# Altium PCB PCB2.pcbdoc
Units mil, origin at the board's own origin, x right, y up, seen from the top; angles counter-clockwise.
Board outline 6605 x 4585 mil, 2 copper layers (Top Layer, Bottom Layer); 123 components, 92 nets, 392 pads, 89 vias.
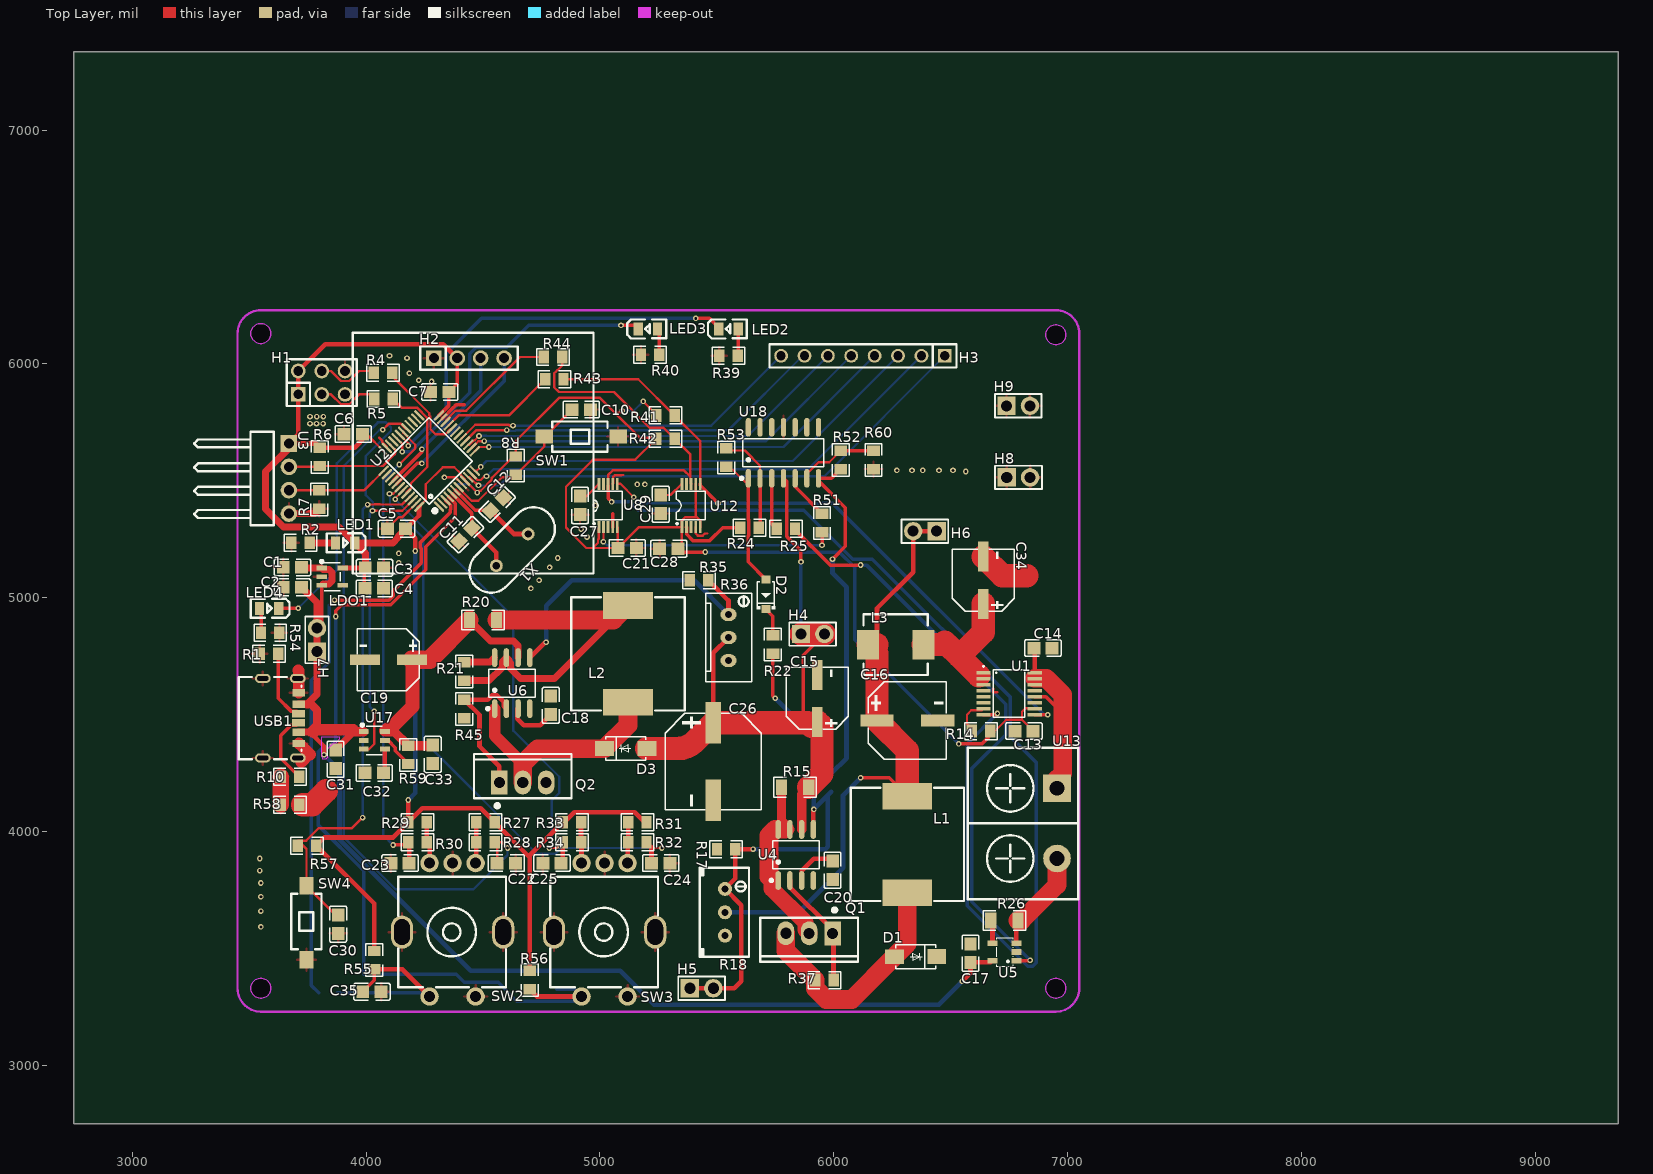
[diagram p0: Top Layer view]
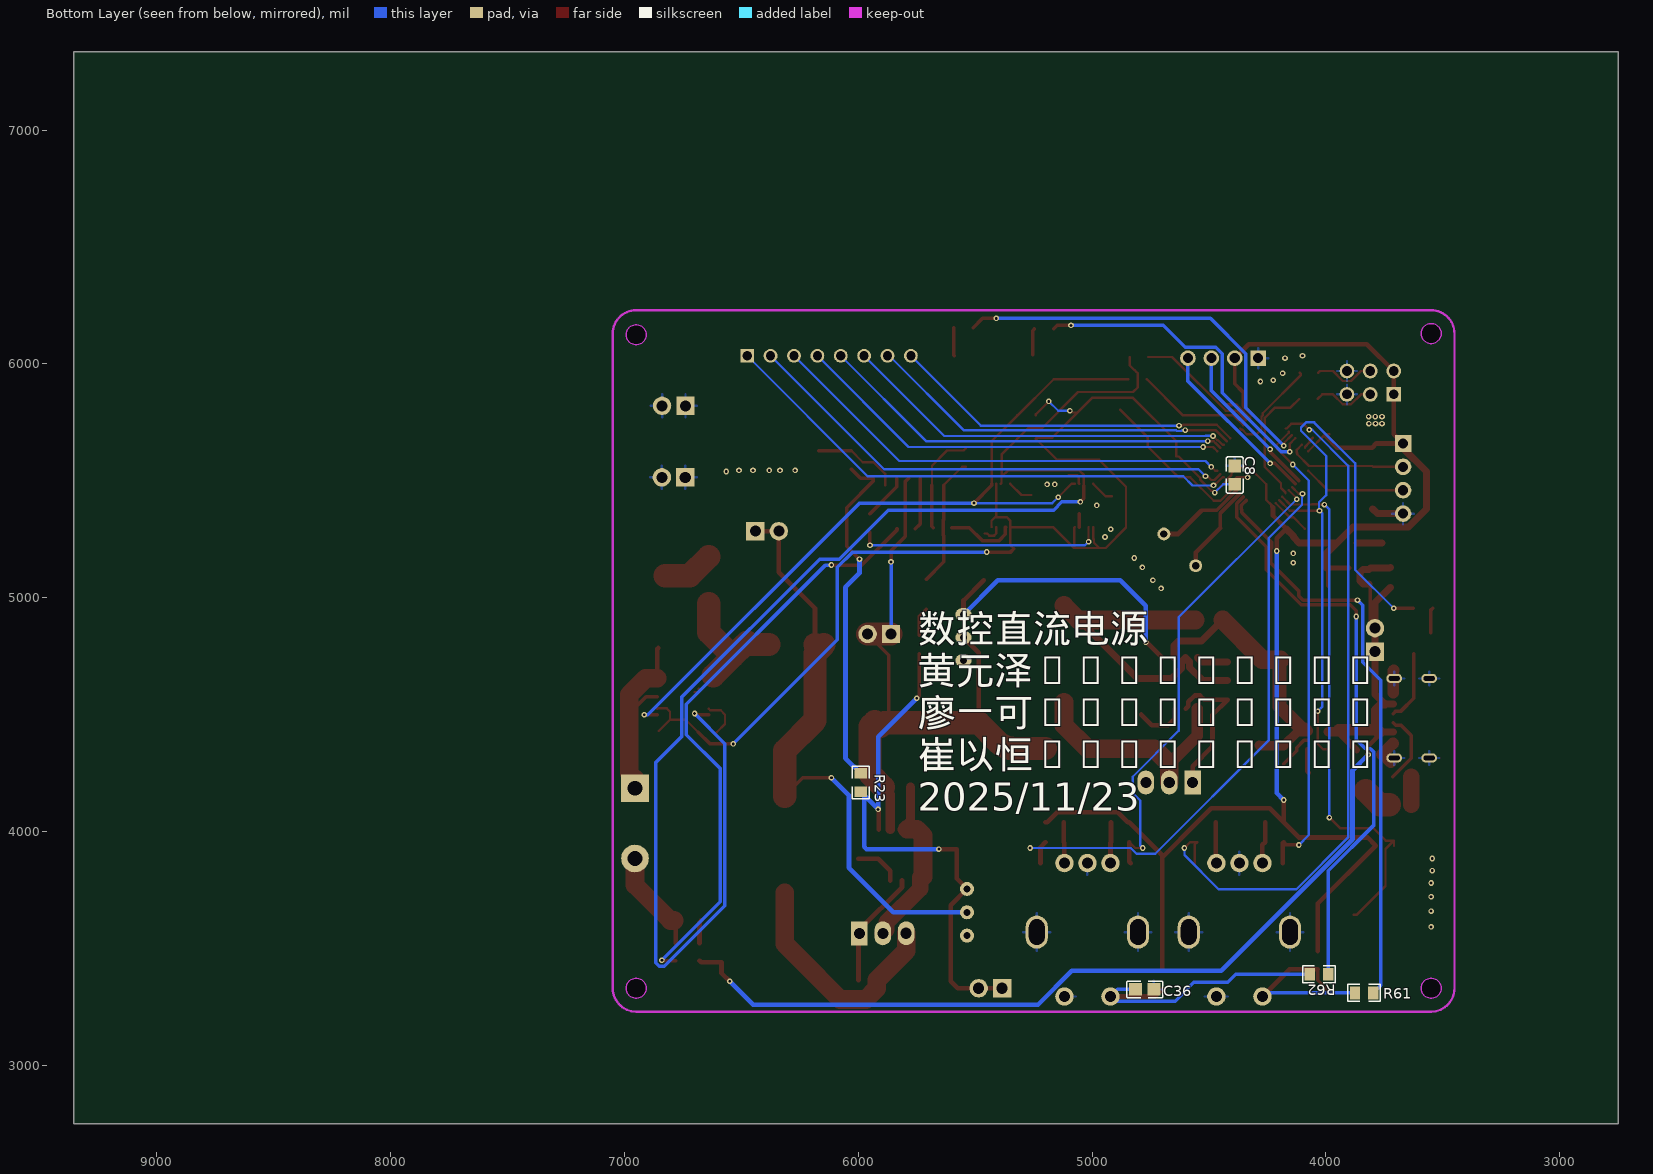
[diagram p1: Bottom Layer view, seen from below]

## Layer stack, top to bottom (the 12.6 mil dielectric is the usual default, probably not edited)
Top Layer: signal copper (thickness not stored)
Dielectric: dielectric 12.6, FR-4, Dk 4.8
Bottom Layer: signal copper (thickness not stored)

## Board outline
9355,2750 2750,2750 2750,7335 9355,7335
cut-out: 3593,6130 cw(c3550,6130) 3507,6130 cw(c3550,6130)
cut-out: 6993,6125 cw(c6950,6125) 6907,6125 cw(c6950,6125)
cut-out: 6993,3330 cw(c6950,3330) 6907,3330 cw(c6950,3330)
cut-out: 3593,3330 cw(c3550,3330) 3507,3330 cw(c3550,3330)

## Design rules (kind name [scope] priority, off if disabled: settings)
BoardOutlineClearance copperThickness1oz [All] p0: genericclearance=10 ignorepadtopadclearanceinfootprint=FALSE except(0: Arc-SplitContinuation Track-SplitContinuation SMDPad-SplitContinuation THPad-SplitContinuation Via-SplitContinuation Fill-SplitContinuation Poly-SplitContinuation Region-SplitContinuation Text-SplitContinuation; 6: Track-CutoutEdge SMDPad-CutoutEdge THPad-CutoutEdge Via-CutoutEdge Region-CutoutEdge; 11.8: Track-OutlineEdge SMDPad-OutlineEdge THPad-OutlineEdge Via-OutlineEdge Fill-OutlineEdge Region-OutlineEdge Poly-OutlineEdge Text-OutlineEdge Fill-CutoutEdge)
BoardOutlineClearance copperThickness2oz [All] p0: genericclearance=10 ignorepadtopadclearanceinfootprint=FALSE except(0: Arc-SplitContinuation Track-SplitContinuation SMDPad-SplitContinuation THPad-SplitContinuation Via-SplitContinuation Fill-SplitContinuation Poly-SplitContinuation Region-SplitContinuation Text-SplitContinuation; 6: Track-CutoutEdge SMDPad-CutoutEdge THPad-CutoutEdge Via-CutoutEdge Region-CutoutEdge; 11.8: Track-OutlineEdge SMDPad-OutlineEdge THPad-OutlineEdge Via-OutlineEdge Fill-OutlineEdge Region-OutlineEdge Poly-OutlineEdge Text-OutlineEdge Fill-CutoutEdge)
Clearance copperThickness1oz [(InNet('+5V') OR InNet('GND') OR InNet('VCC') OR InNet('RESET') OR InNet('OSCIN') OR InNet('OSCOUT') OR InNet('IN-') OR InNet('VOUT') OR InNet('$1N15305') OR InNet('$1N14143') OR InNet('PA8') OR InNet('PA9') OR InNet('PB6') OR InNet('PB7') OR InNet('$1N21810') OR InNet('$1N23905') OR InNet('$1N5169') OR InNet('$1N14411') OR InNet('$1N14439') OR InNet('$1N3483') OR InNet('$1N3468') OR InNet('PB4') OR InNet('PB5') OR InNet('PA0') OR InNet('PA1') OR InNet('PA2') OR InNet('PA3') OR InNet('PA4') OR InNet('PA5') OR InNet('PA6') OR InNet('PA7') OR InNet('I-FB') OR InNet('$1N21463') OR InNet('$1N3407') OR InNet('PB0') OR InNet('$1N36216') OR InNet('PB1') OR InNet('$1N36298') OR InNet('STEP-DOWN1') OR InNet('$1N26107') OR InNet('$1N15295') OR InNet('$1N3381') OR InNet('BOOT1') OR InNet('BOOT0') OR InNet('SWDIO') OR InNet('SWCLK') OR InNet('$1N3384') OR InNet('$1N3763') OR InNet('$1N12640') OR InNet('DAC-VOUT1') OR InNet('$1N14642') OR InNet('DAC-IOUT') OR InNet('$1N14584') OR InNet('I-VOUT') OR InNet('$1N19210') OR InNet('$1N19205') OR InNet('$1N19652') OR InNet('$1N19642') OR InNet('$1N21716') OR InNet('$1N26297') OR InNet('SCL2') OR InNet('SDA2') OR InNet('PB10') OR InNet('PB11') OR InNet('$1N65373') OR InNet('DAC-VOUT') OR InNet('$1N65377') OR InNet('VBAT') OR InNet('PC13') OR InNet('PC14') OR InNet('PC15') OR InNet('PB12') OR InNet('PB13') OR InNet('PB14') OR InNet('PB15') OR InNet('PA10') OR InNet('PA11') OR InNet('PA12') OR InNet('PA15') OR InNet('PB3') OR InNet('PB8') OR InNet('PB9') OR InNet('V-UP') OR InNet('$1N72576') OR InNet('$1N76167') OR InNet('$1N76238') OR InNet('PGND') OR InNet('+5V-SWITCH') OR InNet('RS+') OR InNet('$1N76827') OR InNet('QOD') OR InNet('VOUT-FILTER'))] p1: gap=7 ignorepadtopadclearanceinfootprint=FALSE except(4: Track-Track; 6: Track-SMDPad SMDPad-SMDPad Track-THPad SMDPad-THPad THPad-THPad Track-Via SMDPad-Via THPad-Via Via-Via SMDPad-Fill THPad-Fill Via-Fill Fill-Fill Track-Region SMDPad-Region THPad-Region Via-Region Region-Region Track-Poly SMDPad-Poly THPad-Poly Via-Poly Fill-Poly Region-Poly Poly-Poly Track-Text SMDPad-Text THPad-Text Via-Text Fill-Text Region-Text Poly-Text Text-Text; 6.9: Track-Hole SMDPad-Hole THPad-Hole Via-Hole Fill-Hole Region-Hole Poly-Hole Text-Hole Sheet-Hole; 11.8: Track-Fill Fill-Region Track-Sheet SMDPad-Sheet THPad-Sheet Via-Sheet Fill-Sheet Region-Sheet Poly-Sheet Text-Sheet)
Clearance copperThickness2oz [All] p1: gap=7 ignorepadtopadclearanceinfootprint=FALSE except(6: Track-SMDPad SMDPad-SMDPad Track-THPad SMDPad-THPad THPad-THPad Track-Via SMDPad-Via THPad-Via Via-Via SMDPad-Fill THPad-Fill Via-Fill Fill-Fill Track-Region SMDPad-Region THPad-Region Via-Region Region-Region Track-Poly SMDPad-Poly THPad-Poly Via-Poly Fill-Poly Region-Poly Poly-Poly Track-Text SMDPad-Text THPad-Text Via-Text Fill-Text Region-Text Poly-Text Text-Text; 6.9: Track-Hole SMDPad-Hole THPad-Hole Via-Hole Fill-Hole Region-Hole Poly-Hole Text-Hole Sheet-Hole; 8: Track-Track; 11.8: Track-Fill Fill-Region Track-Sheet SMDPad-Sheet THPad-Sheet Via-Sheet Fill-Sheet Region-Sheet Poly-Sheet Text-Sheet)
DiffPairsRouting differentialPair [All] p1: maxuncoupledlength=10 minlimit=6 maxlimit=6 mostfreqgap=6 toplayer_minwidth=5 toplayer_prefwidth=10 toplayer_maxwidth=100 bottomlayer_minwidth=5 bottomlayer_prefwidth=10 bottomlayer_maxwidth=100
PasteMaskExpansion pasteMaskExpansion [All] p1: expansion=0
PlaneConnect innerPlane [All] p1: planeconnectstyle=Relief reliefexpansion=20 reliefentries=4 reliefconductorwidth=10 reliefairgap=10
PolygonConnect PGND [All] p1: connectstyle=Direct reliefentries=4 reliefconductorwidth=10 polygonreliefangle="90 Angle" airgapwidth=10
PolygonConnect GND [All] p1: connectstyle=Relief reliefentries=4 reliefconductorwidth=10 polygonreliefangle="90 Angle" airgapwidth=10
RoutingVias viaSize [All] p1: viastyle="Through Hole" holewidth=12.0078 minholewidth=11.811 maxholewidth=248.0314 width=24.0158 minwidth=19.685 maxwidth=393.7008
SolderMaskExpansion solderMaskExpansion [All] p1: useseparateexpansions=TRUE expansion=2 expansionbottom=2
Width copperThickness1oz [All] p1: maxlimit=200 minlimit=5 preferedwidth=10
Width P [All] p1: maxlimit=200 minlimit=8 preferedwidth=20

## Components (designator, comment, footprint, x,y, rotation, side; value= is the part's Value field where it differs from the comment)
C1 "0805B104K500NT" C0805 3685,5130 r0 top
C2 "CL21B105KBFNNNE" C0805 3685,5045 r0 top
C3 "CL21B105KBFNNNE" C0805 4035.76,5128.37 r180 top
C4 "0805B104K500NT" C0805 4035,5040 r180 top
C5 "0805B104K500NT" C0805 4130,5295 r0 top
C6 "0805B104K500NT" C0805 3945,5700 r0 top
C7 "0805B104K500NT" C0805 4315,5880 r0 top
C8 "0805B104K500NT" C0805 4390,5525 r270 bottom
C10 "0805B104K500NT" C0805 4920,5805 r0 top
C11 "0805CG220J500NT" C0805 4425,5270 r45 top
C12 "0805CG220J500NT" C0805 4560,5400 r225 top
C13 "0805B104K500NT" C0805 6813.74,4430 r0 top
C14 "0805B474K500NT" C0805 6895,4785 r180 top
C15 "MA35V100M6X8" CAP-SMD_BD6.3-L6.6-W6.6-RD 5930,4570 r270 top
C16 "MA25V470M8x10" CAP-SMD_BD8.0-L8.3-W8.3-LS9.0-FD_H10.5 6315,4475 r0 top
C17 "0805B104K500NT" C0805 6585,3480 r90 top
C18 "0805B152K500NT" C0805 4790,4540 r270 top
C19 "MA35V100M6X8" CAP-SMD_BD6.3-L6.6-W6.6-RD 4095,4735 r0 top
C20 "0805B471K500NT" C0805 5995,3835 r90 top
C21 "0805B104K500NT" C0805 5116.32,5213.02 r180 top
C22 "0805B103K500NT_C52278" C0805 4600,3865 r0 top
C23 "0805B103K500NT_C52278" C0805 4145,3865 r0 top
C24 "0805B103K500NT_C52278" C0805 5260,3865 r0 top
C25 "0805B103K500NT_C52278" C0805 4795,3865 r0 top
C26 "MA35V330M10x10" CAP-SMD_BD10.0-L10.3-W10.3-FD-LS11.0_H12.0 5485,4300 r270 top
C27 "0805B224K500NT" C0805 4915,5395 r90 top
C28 "0805B104K500NT" C0805 5295,5210 r0 top
C29 "0805B224K500NT" C0805 5260,5400 r90 top
C30 "0805B104K500NT" C0805 3880.63,3604.37 r270 top
C31 "CL21B105KBFNNNE" C0805 3869.59,4308.81 r90 top
C32 "0805B471K500NT" C0805 4034.11,4251.28 r180 top
C33 "CL21A106KAYNNNE_C15850" C0805 4285,4330 r270 top
C34 "MA35V100M6X8" CAP-SMD_BD6.3-L6.6-W6.6-RD 6640,5075 r270 top
C35 "0805B103K500NT_C52278" C0805 4025,3315 r0 top
C36 "0805B103K500NT_C52278" C0805 4775,3325 r180 bottom
D1 "SS34_C7420365" SMA_L4.3-W2.6-LS5.0-FD 6350,3465 r0 top
D2 "1N4148W_C7420318" SOD-123_L2.7-W1.6-LS3.7-FD 5710,5015 r270 top
D3 "SS34_C7420365" SMA_L4.3-W2.6-LS5.0-FD 5110,4355 r180 top
H1 "210-72-03GB01" HDR-TH_6P-P2.54-V-R2-C3-S2.54_A2541WV-2X3P 3810,5920 r0 top
H2 "2.54-1*4P母" HDR-TH_4P-P2.54-V-F 4440,6025 r0 top
H3 "PZ254V-11-08P" HDR-TH_8P-P2.54-V-M 6125,6035 r180 top
H4 "PZ254V-11-02P" HDR-TH_2P-P2.54-V-M 5910,4845 r0 top
H5 "PZ254V-11-02P" HDR-TH_2P-P2.54-V-M 5435,3330 r0 top
H6 "PZ254V-11-02P" HDR-TH_2P-P2.54-V-M 6390,5285 r180 top
H7 "PZ254V-11-02P" HDR-TH_2P-P2.54-V-M 3790,4820 r90 top
H8 "PZ254V-11-02P" HDR-TH_2P-P2.54-V-M 6790,5515 r0 top
H9 "PZ254V-11-02P" HDR-TH_2P-P2.54-V-M 6789,5821.15 r0 top
L1 "SMDRI127-221MT" IND-SMD_L12.3-W12.3_SMDRI127 6315,3945 r270 top
L2 "SMDRI127-221MT" IND-SMD_L12.3-W12.3_SMDRI127 5120,4760 r90 top
L3 "FXL0630-1R0-M" IND-SMD_L7.0-W6.6 6265,4800 r0 top
LDO1 "ME6211C33M5G-N" SOT-23-5_L3.0-W1.7-P0.95-LS2.8-BL 3855,5090 r270 top
LED1 "NCD0805B2" LED0805-R-RD 3910,5235 r180 top
LED2 "NCD0805B2" LED0805-R-RD 5550,6150 r0 top
LED3 "NCD0805B2" LED0805-R-RD 5205,6150 r0 top
LED4 "NCD0805B2" LED0805-R-RD 3585,4955 r180 top
Q1 "TIP31C_C963401" TO-220-3_L10.0-W4.5-P2.54-L 5895,3565 r180 top
Q2 "TIP31C_C963401" TO-220-3_L10.0-W4.5-P2.54-L 4670,4210 r0 top
R1 "0805W8F5101T5E" R0805 3585,4760 r180 top
R2 "0805W8F1001T5E" R0805 3720,5235 r180 top
R4 "0805W8F1002T5E_C17414" R0805 4072.5,5962.5 r0 top
R5 "0805W8F1002T5E_C17414" R0805 4075,5850 r180 top
R6 "0805W8F1002T5E_C17414" R0805 3801.39,5603.01 r270 top
R7 "0805W8F1002T5E_C17414" R0805 3800,5420 r90 top
R8 "0805W8F1002T5E_C17414" R0805 4640,5565 r90 top
R10 "0805W8F5101T5E" R0805 3675,4235 r180 top
R14 "0805W8F4701T5E" R0805 6630,4430 r180 top
R15 "FRL1206FR220TS" R1206 5835,4190 r180 top
R17 "0805W8F1002T5E_C17414" R0805 5540,3925 r0 top
R18 "3296W-1-104LF" RES-ADJ-TH_3296W 5535,3655 r0 top
R20 "FRL1206FR220TS" R1206 4500,4905 r180 top
R21 "0805W8F1800T5E" R0805 4420,4685 r270 top
R22 "0805W8F1001T5E" R0805 5740,4800 r90 top
R23 "0805W8F1002T5E_C17414" R0805 5990,4210 r270 bottom
R24 "0805W8F1001T5E" R0805 5640,5300 r0 top
R25 "0805W8F1001T5E" R0805 5795,5295 r180 top
R26 "RE1206F1R050" R1206 6730,3620 r180 top
R27 "0805W8F1002T5E_C17414" R0805 4510,4040 r0 top
R28 "0805W8F1002T5E_C17414" R0805 4510,3955 r180 top
R29 "0805W8F1002T5E_C17414" R0805 4220,4040 r0 top
R30 "0805W8F1002T5E_C17414" R0805 4220,3955 r0 top
R31 "0805W8F1002T5E_C17414" R0805 5160,4040 r0 top
R32 "0805W8F1002T5E_C17414" R0805 5160,3955 r180 top
R33 "0805W8F1002T5E_C17414" R0805 4880,4040 r0 top
R34 "0805W8F1002T5E_C17414" R0805 4880,3955 r0 top
R35 "0805W8F1002T5E_C17414" R0805 5423.74,5075 r0 top
R36 "3296W-1-104_C48997936" RES-ADJ-TH_3296W-1-203 5550,4830 r90 top
R37 "0805W8F1000T5E" R0805 5960,3365 r0 top
R39 "0805W8F1001T5E" R0805 5550,6035 r180 top
R40 "0805W8F1001T5E" R0805 5215,6040 r180 top
R41 "0805W8F1002T5E_C17414" R0805 5280,5780 r0 top
R42 "0805W8F1002T5E_C17414" R0805 5280,5680 r0 top
R43 "0805W8F1000T5E" R0805 4805,5935 r180 top
R44 "0805W8F1000T5E" R0805 4800,6030 r180 top
R45 "0805W8F1800T5E" R0805 4420,4525 r270 top
R51 "0805W8F1001T5E" R0805 5950,5320 r90 top
R52 "0805W8F1001T5E" R0805 6030,5590 r270 top
R53 "0805W8F1001T5E" R0805 5540,5600 r270 top
R54 "0805W8F1001T5E" R0805 3590,4850 r0 top
R55 "0805W8F1002T5E_C17414" R0805 4035,3450 r90 top
R56 "0805W8F1002T5E_C17414" R0805 4700,3365 r270 top
R57 "0805W8F1002T5E_C17414" R0805 3747.89,3940.15 r0 top
R58 "Res_0805" R0805 3675,4115 r0 top
R59 "0805W8F1800T5E" R0805 4179.89,4328.35 r270 top
R60 "0805W8F1001T5E" R0805 6170,5590 r90 top
R61 "0805W8F1002T5E_C17414" R0805 3836.26,3310 r0 bottom
R62 "0805W8F1002T5E_C17414" R0805 4030,3390 r0 bottom
SW1 "TS-1101-C-W" SW-SMD_L6.0-W3.3-LS8.0 4920,5690 r0 top
SW2 "EC11N1525404" SW-TH_EC11NXXXX 4370,3580 r180 top
SW3 "EC11N1525404" SW-TH_EC11NXXXX 5020,3580 r180 top
SW4 "TS-1101-C-W" SW-SMD_L6.0-W3.3-LS8.0 3745,3610 r270 top
U1 "INA260AIPWR" TSSOP-16_L5.0-W4.4-P0.65-LS6.4-BL-1 6750,4590 r270 top
U2 "STM32F103C8T6" LQFP-48_L7.0-W7.0-P0.50-LS9.0-BL 4270,5585 r45 top
U3 "2541WR-04P" HDR-TH_4P-P2.54-H-M-W10.4-N 3670,5510 r270 top
U4 "MC34063ADR" SOIC-8_L4.9-W3.9-P1.27-LS6.0-BL 5837.74,3900.11 r0 top
U5 "INA180A3IDBVR" SOT-23-5_L3.0-W1.7-P0.95-LS2.8-BR 6730,3485 r0 top
U6 "MC34063ADR" SOIC-8_L4.9-W3.9-P1.27-LS6.0-BL 4625,4635 r0 top
U8 "DAC60501MDGSR" VSSOP-10_L3.0-W3.0-P0.50-LS4.9-BL 5035,5395 r0 top
U12 "DAC60501MDGSR" VSSOP-10_L3.0-W3.0-P0.50-LS4.9-BL 5390,5395 r0 top
U13 "KF7.62-2P" CONN-TH_KF7.62-2P 6955,4035 r270 top
U17 "TPS22810DBVR" SOT-23-6_L2.9-W1.6-P0.95-LS2.8-BL 4035,4390 r270 top
U18 "LM324DT" SOIC-14_L8.7-W3.9-P1.27-LS6.0-BL 5785,5620 r0 top
USB1 "UKDBBTAAA" USB-C-SMD 3635,4485 r270 top
X1 "YG8MLBBE2X" CRYSTAL-TH_L11.1-W4.7-P4.88 4625,5205 r225 top

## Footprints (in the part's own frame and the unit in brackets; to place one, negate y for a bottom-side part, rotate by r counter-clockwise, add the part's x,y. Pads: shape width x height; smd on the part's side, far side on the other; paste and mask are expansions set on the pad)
C0805 [mm]
  rect 1.41x1.35 smd: 1(-1,0) 2(1,0)
  silkscreen extent -1.96,-0.9 1.96,0.9
CAP-SMD_BD6.3-L6.6-W6.6-RD [mm]
  rect 3.26x1.15 smd: 1(2.555,0) 2(-2.555,0)
  silkscreen extent -3.39,-3.38 3.36,3.38
CAP-SMD_BD8.0-L8.3-W8.3-LS9.0-FD_H10.5 [mm]
  rect 3.61x1.26 smd: 1(-3.295,0) 2(3.295,0)
  silkscreen extent -4.23,-4.23 4.23,4.23
CAP-SMD_BD10.0-L10.3-W10.3-FD-LS11.0_H12.0 [mm]
  rect 4.5x1.65 smd: 1(-4.2,0) 2(4.2,0)
  silkscreen extent -5.23,-5.23 5.23,5.23
CONN-TH_KF7.62-2P [mm]
  rect 3x3 hole 1.6: 1(-3.81,0)
  round 3 hole 1.6: 2(3.81,0)
  silkscreen extent -8.22,-9.7 8.22,2.3
CRYSTAL-TH_L11.1-W4.7-P4.88 [mm]
  round 1.4 hole 0.8: 1(-2.44,0) 2(2.44,0)
  silkscreen extent -5.58,-2.35 5.61,2.35
HDR-TH_2P-P2.54-V-M [mm]
  rect 2x2 hole 1.2: 1(-1.27,0)
  round 2 hole 1.2: 2(1.27,0)
  silkscreen extent -2.54,-1.27 2.54,1.27
HDR-TH_4P-P2.54-H-M-W10.4-N [mm]
  rect 1.8x1.8 hole 1.1: 1(-3.81,0)
  round 1.8 hole 1.1: 2(-1.27,0) 3(1.27,0) 4(3.81,0)
  silkscreen extent -5.09,-10.27 5.07,-1.65
HDR-TH_4P-P2.54-V-F [mm]
  rect 1.7x1.7 hole 1.1: 1(-3.81,0)
  round 1.7 hole 1.1: 2(-1.27,0) 3(1.27,0) 4(3.81,0)
  silkscreen extent -5.29,-1.27 5.29,1.27
HDR-TH_6P-P2.54-V-R2-C3-S2.54_A2541WV-2X3P [mm]
  rect 1.6x1.6 hole 1.05: 1(-2.54,-1.27)
  round 1.6 hole 1.05: 2(-2.54,1.27) 3(0,-1.27) 4(0,1.27) 5(2.54,-1.27) 6(2.54,1.27)
  silkscreen extent -3.81,-2.54 3.81,2.54
HDR-TH_8P-P2.54-V-M [mm]
  rect 1.5x1.5 hole 1: 1(-8.89,0)
  round 1.5 hole 1: 2(-6.35,0) 3(-3.81,0) 4(-1.27,0) 5(1.27,0) 6(3.81,0) 7(6.35,0) 8(8.89,0)
  silkscreen extent -10.16,-1.27 10.16,1.27
IND-SMD_L7.0-W6.6 [mm]
  rect 2.4x3.2 smd: 1(-3,0) 2(3,0)
  silkscreen extent -3.5,-3.3 3.5,3.3
IND-SMD_L12.3-W12.3_SMDRI127 [mm]
  rect 2.9x5.4 smd: 1(-5.25,0) 2(5.25,0)
  silkscreen extent -6.15,-6.15 6.15,6.15
LED0805-R-RD [mm]
  rect 1x1.4 smd: 1(1.05,0) 2(-1.05,0)
  silkscreen extent -2.22,-1.04 1.99,1.01
LQFP-48_L7.0-W7.0-P0.50-LS9.0-BL [mm]
  oval 0.27x1.5 smd: 1(-2.75,-4.25) 2(-2.25,-4.25) 3(-1.75,-4.25) 4(-1.25,-4.25) 5(-0.75,-4.25) 6(-0.25,-4.25) 7(0.25,-4.25) 8(0.75,-4.25) 9(1.25,-4.25) 10(1.75,-4.25) 11(2.25,-4.25) 12(2.75,-4.25) 25(2.75,4.25) 26(2.25,4.25) 27(1.75,4.25) 28(1.25,4.25) 29(0.75,4.25) 30(0.25,4.25) 31(-0.25,4.25) 32(-0.75,4.25) 33(-1.25,4.25) 34(-1.75,4.25) 35(-2.25,4.25) 36(-2.75,4.25)
  oval 1.5x0.27 smd: 13(4.25,-2.75) 14(4.25,-2.25) 15(4.25,-1.75) 16(4.25,-1.25) 17(4.25,-0.75) 18(4.25,-0.25) 19(4.25,0.25) 20(4.25,0.75) 21(4.25,1.25) 22(4.25,1.75) 23(4.25,2.25) 24(4.25,2.75) 37(-4.25,2.75) 38(-4.25,2.25) 39(-4.25,1.75) 40(-4.25,1.25) 41(-4.25,0.75) 42(-4.25,0.25) 43(-4.25,-0.25) 44(-4.25,-0.75) 45(-4.25,-1.25) 46(-4.25,-1.75) 47(-4.25,-2.25) 48(-4.25,-2.75)
  silkscreen extent -3.59,-4.46 3.3,3.34
R0805 [mm]
  rect 1.133x1.377 smd: 1(-1,0) 2(1,0)
  silkscreen extent -1.76,-0.92 1.76,0.92
R1206 [mil]
  rect 47.54x66.97 smd: 1(-58.22,0) 2(58.22,0)
  silkscreen extent -91,-42 91,42
RES-ADJ-TH_3296W [mil]
  round 60 hole 30: 1(0,100.01) 2(0,0.01) 3(0,-99.99)
  silkscreen extent -108,-190 102,190
RES-ADJ-TH_3296W-1-203 [mm]
  oval 1.4x1.75 hole 0.8: 1(-2.5,0) 2(0,0) 3(2.5,0)
  silkscreen extent -4.83,-2.53 4.83,2.48
SMA_L4.3-W2.6-LS5.0-FD [mm]
  rect 2.046x1.62 smd: 1(-2.304,-0.009) 2(2.304,0.009)
  silkscreen extent -2.17,-1.32 2.19,1.29
SOD-123_L2.7-W1.6-LS3.7-FD [mm]
  rect 0.88x0.96 smd: 1(-1.61,0) 2(1.61,0)
  silkscreen extent -1.38,-1 1.6,1
SOIC-8_L4.9-W3.9-P1.27-LS6.0-BL [mm]
  oval 0.588x2.045 smd: 1(-1.905,-2.772) 2(-0.635,-2.772) 3(0.635,-2.772) 4(1.905,-2.772) 5(1.905,2.772) 6(0.635,2.772) 7(-0.635,2.772) 8(-1.905,2.772)
  silkscreen extent -2.8,-2.92 2.53,1.52
SOIC-14_L8.7-W3.9-P1.27-LS6.0-BL [mil]
  oval 22.6x80.24 smd: 1(-150,-109.02) 2(-100,-109.02) 3(-50,-109.02) 4(0,-109.02) 5(50,-109.02) 6(100,-109.02) 7(150,-109.02) 8(150,109.02) 9(100,109.02) 10(50,109.02) 11(0,109.02) 12(-50,109.02) 13(-100,109.02) 14(-150,109.02)
  silkscreen extent -185,-115 173,60
SOT-23-5_L3.0-W1.7-P0.95-LS2.8-BL [mm]
  rect 0.49x1.157 smd: 1(-0.95,-1.154) 2(0,-1.154) 3(0.95,-1.154)
  rect 0.49x1.175 smd: 4(0.95,1.154) 5(-0.95,1.154)
  silkscreen extent -1.8,-1.29 1.53,0.85
SOT-23-5_L3.0-W1.7-P0.95-LS2.8-BR [mm]
  rect 1.1x0.6 smd: 1(1.3,-0.95) 2(1.3,0) 3(1.3,0.95) 4(-1.3,0.95) 5(-1.3,-0.95)
  silkscreen extent -0.9,-1.55 0.9,1.55
SOT-23-6_L2.9-W1.6-P0.95-LS2.8-BL [mil]
  rect 20.95x42.2 smd: 1(-37.4,-45.24) 2(0,-45.24) 3(37.4,-45.24) 4(37.4,45.24) 5(0,45.24) 6(-37.4,45.24)
  silkscreen extent -72,-57 61,35
SW-SMD_L6.0-W3.3-LS8.0 [mm]
  rect 1.9x1.5 smd: 1(-4,0) 2(4,0)
  silkscreen extent -3.14,-1.67 2.86,1.63
SW-TH_EC11NXXXX [mm]
  round 2 hole 1.2: A(-2.5,-7.25) B(2.5,-7.25) C(0,-7.25) D(-2.5,7.25) E(2.5,7.25)
  oval 2.4x3.6 hole 1.7 slot 2.8 at 90 deg: EH(-5.5,0.25) EH(5.5,0.25)
  silkscreen extent -5.8,-5.75 5.9,6.25
TO-220-3_L10.0-W4.5-P2.54-L [mm]
  rect 1.8x2.6 hole 1.2: 1(-2.54,0.005)
  oval 1.8x2.6 hole 1.2: 2(0,0.005)
  oval 1.8x2.6 hole 1.2 copper offset 0,0: 3(2.54,-0.005)
  silkscreen extent -5.3,-2.73 5.3,3.09
TSSOP-16_L5.0-W4.4-P0.65-LS6.4-BL-1 [mm]
  rect 0.364x1.56 smd: 1(-2.275,-2.78) 2(-1.625,-2.78) 3(-0.975,-2.78) 4(-0.325,-2.78) 5(0.325,-2.78) 6(0.975,-2.78) 7(1.625,-2.78) 8(2.275,-2.78) 9(2.275,2.78) 10(1.625,2.78) 11(0.975,2.78) 12(0.325,2.78) 13(-0.325,2.78) 14(-0.975,2.78) 15(-1.625,2.78) 16(-2.275,2.78)
  silkscreen extent -3.03,-2.85 2.58,1.7
USB-C-SMD [mm]
  oval 1x1.7 hole 0.5 slot 1.2 at 90 deg: 1(-4.32,1.849) 2(-4.32,-1.951) 3(4.32,-1.951) 4(4.32,1.849)
  rect 0.8x1.4 smd: A5(-0.5,1.947) A9(1.52,1.948) A12(2.75,1.949) B5(0.5,1.947) B9(-1.52,1.951) B12(-2.75,1.949)
  silkscreen extent -4.47,-4.55 4.47,2.25
VSSOP-10_L3.0-W3.0-P0.50-LS4.9-BL [mm]
  rect 0.3x1.3 smd: 1(-1,-2.35) 2(-0.5,-2.35) 3(0,-2.35) 4(0.5,-2.35) 5(1,-2.35) 6(1,2.35) 7(0.5,2.35) 8(0,2.35) 9(-0.5,2.35) 10(-1,2.35)
  silkscreen extent -1.62,-2.08 1.52,1.54

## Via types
v1: diameter 24.02, hole 12.01, Top Layer to Bottom Layer, 89 vias

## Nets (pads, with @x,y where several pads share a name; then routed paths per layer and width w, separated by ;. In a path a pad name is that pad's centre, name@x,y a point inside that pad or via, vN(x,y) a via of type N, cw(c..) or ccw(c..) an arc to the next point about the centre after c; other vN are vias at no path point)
$1N3381: R1.1 USB1.A5 | length 304.4
  Top Layer w15: R1.1 3624.37,4569.9 3678.66,4515.61 3700.73,4515.61 USB1.A5
$1N3384: R10.1 USB1.B5 | length 307.9
  Top Layer w15: USB1.B5 3700.72,4454.39 3678.56,4454.39 3635,4410.83 3635,4314.37 R10.1
$1N3407: LED1.1 R2.1 | length 107.3
  Top Layer w30: R2.1 LED1.1@3866.69,5235
$1N3468: H1.4 R4.1 | length 261.4
  Top Layer w10: H1.4 3849.92,5970 3892.4,5927.52 3927.6,5927.52 3970.08,5970 4025.63,5970 R4.1
$1N3483: H1.3 R5.2 | length 269.1
  Top Layer w10: H1.3 3849.92,5870 3892.4,5827.52 3927.6,5827.52 3970.08,5870 4015.63,5870 R5.2
$1N3763: R14.2 U1.7 | length 171.1
  Top Layer w10: R14.2@6605.63,4425 6570,4460.63 6570,4500 6588.58,4518.58 6633.11,4518.58 U1.7
$1N5169: D1.1 L1.2 Q1.3 R37.1 | length 1018.7
  Top Layer w80: Q1.3 5794.99,3490.64 R37.1 5920.63,3329.31 5968.13,3281.81 6076.48,3281.81 D1.1 6315,3520.34 L1.2
$1N12640: R21.1 U6.8 | length 138.2
  Top Layer w30: R21.1 4530.22,4724.37 U6.8
$1N14143: C20.2 U4.3 | length 200.4
  Top Layer w20: U4.3 5862.74,3832.74 5914.37,3884.37 C20.2@6000,3884.37
$1N14411: D2.1 R53.2 U18.1 | length 562.8
  Top Layer w10: R53.2 5555.35,5560.63 U18.1@5635,5480.98
  Top Layer w15: U18.1@5635,5480.98 5635,5334.1 5636.41,5332.69 5636.41,5267.31 5635,5265.9 5635,5153.39 D2.1
$1N14439: D2.2 R22.2 | length 124.7
  Top Layer w15: D2.2 5740,4921.61 R22.2
$1N14584: R25.2 U18.3 | length 224.5
  Top Layer w15: U18.3 5735,5315.63 R25.2
$1N14642: R24.2 R53.1 U18.2 | length 443.1
  Top Layer w10: R53.1 5549.37,5630 5620,5630 5685,5565 U18.2@5685,5480.98
  Top Layer w15: R24.2 5685,5305.63 U18.2@5685,5480.98
$1N15295: Q2.1 R45.1 U6.2 | length 637.3
  Top Layer w20: Q2.1 4569.99,4280.01 4485,4365 4485,4499.37 R45.1 4520.86,4564.37 4538.58,4582.09 4561.42,4582.09 4589.02,4554.49 4589.02,4536.83 U6.2
$1N15305: C18.2 U6.3 | length 216.5
  Top Layer w20: U6.3@4646.72,4525.85 4646.72,4483.28 4675,4455 4744.37,4455 C18.2
$1N19205: R29.2 R30.2 SW2.B | length 179.6
  Top Layer w20: R29.2 R30.2 4271.57,3942.8 SW2.B
$1N19210: R27.1 R28.2 SW2.A | length 175.5
  Top Layer w20: SW2.A 4470.63,3867.64 R28.2 R27.1
$1N19642: R33.2 R34.2 SW3.B | length 175.5
  Top Layer w20: R33.2 R34.2 4921.57,3952.8 SW3.B
$1N19652: R31.1 R32.2 SW3.A | length 175.5
  Top Layer w20: SW3.A 5118.42,3952.79 R32.2 R31.1
$1N21463: L2.2 R20.1 R21.2 U6.7 | length 1421
  Top Layer w30: R21.2 4526.21,4645.63 4582.56,4701.98 4582.56,4726.71 U6.7 4610.98,4733.17 4610.98,4727.99 4617.44,4721.53 4617.44,4697.56 4660,4655 4805,4655 5045,4895
  Top Layer w80: R20.1 5058.31,4905 L2.2
$1N21716: R35.2 R36.3 U6.5 | length 1321.1
  Top Layer w20: U6.5 4765.85,4810 v1(4770,4810) ; R35.2 5550,4988.11 R36.3
  Bottom Layer w20: v1(4770,4810) 4770,4965 4880,5075 5403.42,5075 R36.3
$1N21810: C27.2 U8.10 | length 102.6
  Top Layer w10: C27.2 4942.48,5434.37 U8.10
$1N23905: C29.2 U12.10 | length 110.6
  Top Layer w10: C29.2 5302.48,5439.37 U12.10
$1N26107: Q1.1 R37.2 U4.2 | length 503.3
  Top Layer w20: U4.2 5812.74,3762.67 5995.01,3580.41 Q1.1 5999.37,3560.44 R37.2
$1N26297: D3.2 L2.1 Q2.2 U6.1 | length 981.8
  Top Layer w50: U6.1 4550,4409.99 4669.99,4289.99
  Top Layer w80: Q2.2 4669.99,4289.99 4734.63,4354.63 D3.2 5120,4455.34 L2.1
$1N36216: LED2.1 R39.1 | length 120.8
  Top Layer w15: R39.1 5591.35,6036.98 LED2.1@5591.35,6155
$1N36298: LED3.1 R40.1 | length 113.3
  Top Layer w15: LED3.1 5254.37,6141.98 R40.1
$1N65373: R51.2 U18.5 | length 199.2
  Top Layer w15: U18.5 5835,5474.37 R51.2
$1N65377: R52.1 R60.2 U18.6 | length 375.2
  Top Layer w10: U18.6@5885,5480.98 5885,5530 5935,5580 5980.63,5580 R52.1
  Top Layer w15: R52.1 R60.2
$1N72576: LED4.1 R54.1 | length 107.9
  Top Layer w15: LED4.1 3550.63,4948.02 R54.1
$1N76167: C35.1 R55.1 R61.2 SW2.E | length 803.1
  Top Layer w15: C35.1 4035,3364.37 R55.1
  Top Layer w20: R55.1 4155.51,3410.63 SW2.E
  Bottom Layer w15: R61.2 4256.14,3310 SW2.E
$1N76238: C36.1 R56.2 R62.2 SW3.E | length 1262.2
  Top Layer w20: R56.2 4731.06,3294.57 SW3.E
  Bottom Layer w15: R62.2 4385,3390 4420,3355 4565,3355 4645,3275 4902.01,3275 SW3.E 4891.14,3325 C36.1
$1N76827: C32.1 U17.4 | length 104.1
  Top Layer w20: C32.1 4080.24,4258.04 U17.4
+5V: C1.2 C2.2 C17.1 C31.2 H7.1 H7.2 LDO1.1 LDO1.3 U5.5 U17.1 USB1.A9 USB1.B9 | length 5224.1
  Top Layer w15: H7.2 3810,4890 LDO1.3@3810,5052.6
  Top Layer w20: 3760.16,4425.16 3820,4365.32 v1(3820,4328.48) ; v1(6550,3360) 6585,3395 C17.1 6671.85,3440.63 U5.5
  Top Layer w30: USB1.A9 3760.16,4425.16 ; USB1.B9 3747.6,4544.84 3790,4587.24 H7.1 H7.2 3790,4979.37 C2.2 ; C1.2 3726.97,5127.4 LDO1.1 3816.35,5120.63 3841.05,5120.63 3853.34,5108.34 3853.34,5071.66 3841.05,5059.37 LDO1.3@3816.35,5059.37 ; C31.2 3948.81,4427.4
  Top Layer w35: 3747.6,4544.84 3765.16,4544.84 3790,4520 3790,4455 3760.16,4425.16
  Top Layer w40: 3948.81,4427.4 U17.1
  Top Layer w50: 3775,4425 3785,4435 3945,4435
  Bottom Layer w20: v1(3820,4328.48) 3885.98,4262.49 3885.98,3967.12 4448.11,3405 5086.27,3405 5231.27,3260 6450,3260 v1(6550,3360)
+5V-SWITCH: C19.1 C33.1 R20.2 R59.1 U6.6 U17.6 | length 1213.3
  Top Layer w30: R20.2 4531.78,4815 4630,4815 4650,4795 U6.6
  Top Layer w40: U17.6 4120.21,4427.4 R59.1 4283.35,4367.72 C33.1
  Top Layer w50: U17.6@4080.24,4431.46 4090.24,4441.46 4104.3,4441.46
  Top Layer w60: 4104.3,4441.46 4198.41,4535.57 4198.41,4732.18 C19.1
  Top Layer w80: C19.1 4271.78,4735 R20.2
BOOT0: R5.1 U2.44 | length 541.2
  Top Layer w10: R5.1 4151.08,5813.29 4217.88,5813.29 4261.67,5769.5 4261.67,5559.15 4192.06,5489.55 4192.06,5470.1 4172.57,5450.6 U2.44
BOOT1: R4.2 U2.20 | length 424.5
  Top Layer w10: R4.2 4106.87,5957.5 4106.87,5952.5 4270,5789.37 4270,5780.99 4275.68,5775.31 4275.68,5720.58 4296.58,5699.69 4338.15,5699.69 4357.65,5719.19 4362.43,5719.19 U2.20
DAC-IOUT: R24.1 U12.2 | length 295
  Top Layer w15: U12.2 5370.61,5302.19 5370.61,5271.3 5396.91,5245 5470,5245 5525,5300 R24.1
DAC-VOUT: R51.1 U8.2 | length 1059.5
  Top Layer w10: v1(5015,5240) 5015,5302.16 U8.2
  Top Layer w15: v1(5950,5225) R51.1
  Bottom Layer w10: v1(5015,5240) 5030,5225 v1(5950,5225)
DAC-VOUT1: R23.1 R52.2 U18.7 | length 1495.2
  Top Layer w15: v1(5995,5165.49) 6050,5220.49 6050,5385 5935,5500 U18.7 5990.35,5510.98 R52.2
  Bottom Layer w20: R23.1 6055,4314.37 6055,5045 5995,5105 v1(5995,5165.49)
GND: C1.1 C2.1 C3.1 C4.1 C5.1 C6.1 C7.1 C8.1 C10.2 C11.1 C12.1 C21.1 C22.2 C23.1 C24.2 C25.1 C27.1 C28.1 C29.1 C30.2 C35.2 C36.2 H1.5 H1.6 H2.1 H8.1 H8.2 H9.1 H9.2 LDO1.2 R1.2 R2.2 R7.1 R10.2 R39.2 R40.2 R54.2 R58.1 R60.1 SW1.2 SW2.C SW2.D SW2.EH SW3.C SW3.D SW3.EH SW4.2 U2.8 U2.23 U2.35 U2.47 U3.4 U8.4 U8.7 U12.4 U18.11 USB1.1 USB1.2 USB1.3 USB1.4 USB1.A12 USB1.B12 | length 1132.4
  Top Layer w10: 4055,5685 4069.55,5670.45 4069.55,5664.96 4089.05,5645.46 U2.35 ; C5.1 4090.63,5295.63 4140,5345 4155.27,5345 U2.47 ; v1(4335,5515) 4381.76,5515 U2.8 ; U8.7 5057.48,5490.31 5057.48,5517.66 5063.91,5524.09 5091.26,5524.09 5092.16,5525 5100,5525 ; U12.4 5409.69,5275.14 5418.92,5265.91 5439.83,5265.91 5448.93,5275 5460,5275
  Top Layer w15: U2.23 4327.98,5768.25 cw(c4341.39,5758.61) 4329.71,5770.29 4371.1,5811.68 cw(c4382.78,5800) 4373.14,5813.41 4384.73,5825 4420,5825 ; U8.4 5054.69,5359.69 5055,5360
  Top Layer w30: U3.4 3779.37,5360 R7.1
  Top Layer w50: USB1.1 USB1.1@3711.74,4651.14 ; 3710,4690 3711.74,4688.26 USB1.1@3711.74,4651.14 ; USB1.A12 3713.27,4376.73 3760,4330 3755,4330 USB1.4@3722.14,4297.14 ; USB1.B12 USB1.1@3711.74,4651.14
  Top Layer w70: R58.1 R10.2
  other v1: 3550,3592.49 3550,3660 3550,3721.37 3550,3780 3545,3833.07 3545,3885 4705,5040 4740,5075 4785,5130 4140,5149.92 4820,5170 4140,5190 4945,5260 4920,5293.49 4979.76,5395 5160,5485 5192.45,5485 6565,5540 6270,5545 6335,5545 6381,5545 6450.14,5545 6510,5545 3760,5745 3787.82,5745 3816.2,5745 3760,5775 3788.87,5775 3817.25,5775 4280,5925 4225,5930 4185,5960 4175,6025 4100,6035
I-FB: H5.1 H5.2 R17.2 R18.1 R22.1 R23.2 U4.5 | length 2396
  Top Layer w15: R22.1 5740,4580 v1(5750,4570)
  Top Layer w20: H5.1 H5.2 5575,3330 5605,3360 5605,3685 R18.1 5579.37,3799.37 R17.2 v1(5655,3925) ; U4.5 5912.74,4092.74 v1(5915,4095)
  Bottom Layer w20: v1(5655,3925) 5964.85,3925 5975,3935.15 R23.2@5975,4155 ; v1(5750,4570) 5915,4405 v1(5915,4095) R23.2@5975,4155 ; R23.2 5975,4155.63 R23.2@5975,4155
I-VOUT: R25.1 U5.1 | length 2532.6
  Top Layer w15: R25.1 5834.37,5290.07 5984.44,5140 v1(6115,5140) ; U5.1 6837.6,3447.6 v1(6840,3450)
  Bottom Layer w15: v1(6115,5140) 6140,5140 6735,4545 6735,4415 6590,4270 6590,3700 v1(6840,3450)
IN-: C14.2 U1.12 U1.14 U1.15 U1.16 U13.1 | length 768.1
  Top Layer w10: U1.15 6859.45,4655.95 U1.16
  Top Layer w15: U1.12 6907.8,4577.2 6955,4530
  Top Layer w20: C14.2 6859.45,4781.18 U1.16
  Top Layer w80: U1.15@6859.45,4655.95 6909.21,4655.95 6980,4585.16 6980,4250 U13.1@6955,4225
OSCIN: C11.2 U2.5 X1.2 | length 387.3
  Top Layer w15: U2.5 4452.84,5360.4 C11.2
  Top Layer w20: C11.2 4557.08,5193.6 X1.2
OSCOUT: C12.2 U2.6 X1.1 | length 388.9
  Top Layer w15: U2.6 4382.6,5459.73 4467.33,5375 4529.32,5375 C12.2
  Top Layer w20: C12.2 4631.4,5272.92 X1.1
PA0: H3.1 U2.10 | length 2282.1
  Top Layer w10: U2.10 4441.81,5515.41 4467.72,5489.5 4471.55,5489.5 v1(4480.53,5480.53)
  Bottom Layer w10: v1(4480.53,5480.53) 4570.53,5480.53 4610,5520 5960,5520 H3.1
PA1: H3.2 U2.11 | length 2154.9
  Top Layer w10: U2.11 4476.75,5503.52 4490.05,5503.52 4506.53,5520 v1(4515,5520)
  Bottom Layer w10: v1(4515,5520) 4545,5550 5890,5550 H3.2
PA2: H3.3 U2.12 | length 2013.8
  Top Layer w10: U2.12 4473.25,5543.25 v1(4490,5560)
  Bottom Layer w10: v1(4490,5560) 4515,5585 5825,5585 H3.3
PA3: H3.4 U2.13 | length 1879.2
  Top Layer w10: U2.13 4483.12,5645 v1(4525,5645)
  Bottom Layer w10: v1(4525,5645) 5785,5645 H3.4
PA4: H3.5 U2.14 | length 1787.4
  Top Layer w10: U2.14 4470.35,5660.08 4470.5,5660.08 4479.63,5669.22 4492.33,5669.22 4493.11,5670 v1(4505,5670)
  Bottom Layer w10: v1(4505,5670) 5710,5670 H3.5
PA5: H3.6 U2.15 | length 1696.2
  Top Layer w10: U2.15 4441.81,5654.59 4461.32,5674.1 4464.7,5674.1 v1(4482.81,5692.21)
  Bottom Layer w10: v1(4482.81,5692.21) 4494.69,5692.21 4495.48,5692.99 4514.52,5692.99 4515.31,5692.21 5632.21,5692.21 H3.6
PA6: H3.7 U2.16 | length 1606.9
  Top Layer w10: U2.16 4471.8,5717.21 v1(4601.62,5717.21)
  Bottom Layer w10: v1(4601.62,5717.21) 4614.66,5717.21 4618.5,5713.37 4637.55,5713.37 4641.39,5717.21 5549.53,5717.21 5867.32,6035 H3.7
PA7: H3.8 U2.17 | length 1515
  Top Layer w10: U2.17 4466.96,5740.2 4611.14,5740.2 4614.98,5736.36 v1(4628.03,5736.36)
  Bottom Layer w10: v1(4628.03,5736.36) 5476.36,5736.36 H3.8
PA8: C22.1 R28.1 U2.29 | length 2983.5
  Top Layer w10: v1(4071.22,5718.52) 4096.39,5743.69 4148.28,5743.69 4167.77,5724.19 U2.29 ; C22.1 4560.63,3943.74 R28.1 4580,3955 v1(4605,3930)
  Bottom Layer w10: v1(4071.22,5718.52) 4058.52,5718.52 3905,5565 3905,3975 4127.07,3752.93 4458.39,3752.93 4605,3899.54 v1(4605,3930)
PA9: C23.2 R30.1 U2.30 | length 2024.6
  Top Layer w10: v1(4141.48,5570) 4210,5638.52 4210,5654.59 4158.64,5705.95 U2.30
  Top Layer w15: v1(4115.63,3942.88) 4168.51,3942.88 R30.1
  Top Layer w20: R30.1 4184.37,3951.26 C23.2
  Bottom Layer w10: v1(4115.63,3942.88) 4072.99,3985.52 4072.99,5501.51 v1(4141.48,5570)
PA10: LED2.2 U2.31 | length 1767.5
  Top Layer w10: U2.31 4180,5661.08 v1(4180,5650)
  Top Layer w15: v1(5410,6195) 5468.65,6195 LED2.2@5508.65,6155
  Bottom Layer w15: v1(4180,5650) 4343.05,5813.05 4343.05,6044.45 4493.6,6195 v1(5410,6195)
PA11: LED3.2 U2.32 | length 1404.5
  Top Layer w10: U2.32 4155,5658.24 v1(4155,5625)
  Top Layer w15: v1(5090,6165) 5148.65,6165 LED3.2
  Bottom Layer w15: v1(4155,5625) 4168.95,5625 4169.44,5624.51 4190.56,5624.51 4443.05,5877 4443.05,6044.45 4470.55,6071.95 4601.95,6071.95 4695,6165 v1(5090,6165)
PA12: U2.33
PA15: U2.38
PB0: U2.18
PB1: U2.19
PB3: U2.39
PB4: H2.3 U2.40 | length 678.1
  Top Layer w15: U2.40 4238.67,5623.27 v1(4238.67,5635)
  Bottom Layer w15: v1(4238.67,5635) 4490,5886.33 H2.3
PB5: H2.4 U2.41 | length 739.6
  Top Layer w15: U2.41 4218.24,5575 v1(4238.67,5575)
  Bottom Layer w15: v1(4238.67,5575) 4590,5926.33 H2.4
PB6: C24.1 R32.1 U2.42 | length 2547.6
  Top Layer w10: v1(4100,5445) 4116.08,5445 U2.42 ; R32.1@5220.63,3933.74 5224.37,3930 v1(5265,3930)
  Top Layer w20: R32.1 5220.63,3933.74 C24.1
  Bottom Layer w10: v1(4100,5445) 4100,5433.24 4102.01,5431.23 4102.01,5397.99 4245,5255 4245,4390 4730,3905 4810,3905 4835,3930 v1(5265,3930)
PB7: C25.2 R34.1 U2.43 | length 2012.3
  Top Layer w10: v1(4125,5421.71) 4125,5426.08 U2.43 ; v1(4783.34,3930) 4815.63,3930 R34.1
  Top Layer w20: C25.2 4840.63,3871.26 R34.1
  Bottom Layer w10: v1(4125,5421.71) 4630,4916.71 4630,4431.2 4826.42,4234.78 4826.42,4164.83 4793.34,4131.74 4793.34,3940 v1(4783.34,3930)
PB8: C30.1 R57.1 SW4.1 U2.45 | length 2277.6
  Top Layer w10: R57.1 R57.1@3708.52,3961.48 ; C30.1 3868.74,3643.74 SW4.1 3745,3925 R57.1@3708.52,3961.48 ; v1(3985,4060) 3940,4015 3797.18,4015 3743.66,3961.48 R57.1@3708.52,3961.48 ; v1(4006.29,5398.71) 4036.2,5398.71 4037.98,5400.49 4057.02,5400.49 4058.8,5398.71 4153.31,5398.71 U2.45
  Bottom Layer w10: v1(3985,4060) 3985,5377.43 v1(4006.29,5398.71)
PB9: LED4.2 U2.46 U17.3 | length 2756.9
  Top Layer w10: U17.3 4012.6,4352.6 4035,4375 v1(4035,4515) ; v1(4027.5,5372.5) 4154.94,5372.5 U2.46
  Top Layer w15: LED4.2 v1(3710,4955)
  Bottom Layer w10: v1(3710,4955) 3875,5120 3875,5575 4050.34,5750.34 4084.66,5750.34 4106.56,5728.44 4106.56,5714.3 3998.24,5605.99 3998.24,5439.27 4029.28,5408.24 4029.28,5374.28 v1(4027.5,5372.5) 4015,5360 4015,4535 v1(4035,4515)
PB10: R43.2 U2.21 | length 493.7
  Top Layer w10: U2.21 4395.41,5780 4610.63,5780 R43.2
PB11: R44.2 U2.22 | length 531.7
  Top Layer w10: U2.22@4341.39,5758.61 4382.78,5800 4427.86,5800 4657.86,6030 R44.2
PB12: U2.25
PB13: U2.26
PB14: U2.27
PB15: U2.28
PC13: U2.2
PC14: R61.1 U2.3 | length 2517.1
  Top Layer w15: v1(3865,4990) 4097.77,4990 4115.61,5007.84 4115.61,5029.05 4235.49,5148.93 4235.49,5210.56 4231.52,5214.54 4231.52,5236.52 4360,5365 4360,5377.55 4361.6,5379.14 4361.6,5394.72 4360,5396.32 4360,5397.56 U2.3
  Bottom Layer w15: R61.1 3765,3341.89 3765,4647.19 3842.85,4725.04 3842.85,4967.85 v1(3865,4990)
PC15: R62.1 U2.4 | length 2512.3
  Top Layer w15: v1(3870,4920) 3870,4945 3895.98,4970.98 4105.65,4970.98 4254.51,5119.85 4254.51,5218.44 4380.61,5344.54 4380.61,5402.59 4379.02,5404.19 4379.02,5405.44 4353.52,5430.94 U2.4
  Bottom Layer w15: v1(3870,4920) 3870,4393.41 3830.56,4353.97 3809.44,4353.97 3794.51,4339.04 3794.51,4028.17 3990.63,3832.05 R62.1
PGND: C13.1 C14.1 C15.2 C16.2 C17.2 C18.1 C19.2 C20.1 C26.2 C31.1 C32.2 C33.2 C34.2 D1.2 Q2.3 R17.1 R26.2 R35.1 R45.2 R58.2 U1.4 U1.5 U1.6 U1.11 U4.4 U5.2 U5.4 U6.4 U17.2 | length 477.2
  Top Layer w10: 6682.24,4610.24 6682.24,4595.35 6699.65,4595.35 6700,4595
  Top Layer w20: R26.2 6678.81,3612.97 U5.4
  Top Layer w100: R58.2@3729.37,4115 3770,4115 3830,4175 ; C34.2 6720.59,5095 6825,5095
QOD: R59.2 U17.5 | length 150.1
  Top Layer w15: U17.5 4093.48,4390 4125,4358.48 4125,4345.24 4179.89,4290.35 R59.2
RESET: C10.1 R8.1 SW1.1 U2.7 | length 683.7
  Top Layer w10: U2.7@4402.84,5462.84 4450.69,5415 4480,5415 4580.63,5515.63 4630,5515.63 R8.1 4762.52,5648.15 SW1.1 4765.63,5690 C10.1
RS+: R26.1 U5.3 U13.2 | length 433.4
  Top Layer w20: U5.3 R26.1@6781.19,3612.97
  Top Layer w80: R26.1 6803.22,3620 6955,3771.78 U13.2
SCL2: R41.2 R43.1 U1.9 U8.6 U12.6 | length 3296.5
  Top Layer w10: R43.1 5164.37,5935 R41.2 5429.36,5670.01 U12.6 ; U8.6 5087.48,5487.52 v1(5145,5430)
  Top Layer w15: U12.6 5429.36,5480.64 v1(5505,5405) ; U1.9 6914.57,4500.43 v1(6915,4500)
  Bottom Layer w10: v1(5145,5430) 5170,5405 v1(5505,5405)
  Bottom Layer w15: v1(5505,5405) 5995,5405 6900,4500 v1(6915,4500)
SDA2: R42.2 R44.1 U1.8 U8.8 U12.8 | length 6034
  Top Layer w10: R44.1 4839.37,5994.37 4818.09,5973.09 4817.53,5973.09 4811.09,5966.66 4811.09,5966.09 4805,5960 4805,5900 4825,5880 5060,5880 5212.5,5727.5 5271.87,5727.5 R42.2 5387.07,5612.3 5387.07,5517.79 ; U8.8 5035.01,5525.01 5055,5545 5359.87,5545 5387.07,5517.79 ; U12.8 5387.2,5490.32 5387.2,5517.66 5387.07,5517.79
  Top Layer w15: U8.8@5034.7,5480 5035.3,5479.41 5035.3,5424.7 v1(5050,5410) ; U1.8 6695.43,4500.43 v1(6700,4505)
  Bottom Layer w15: v1(5050,5410) 5128.95,5410 5163.95,5375 5871.89,5375 6081.4,5165.49 6164.51,5165.49 6754.02,4575.98 6754.02,4407.12 6865.49,4295.65 6865.49,3439.44 6850.56,3424.51 6829.44,3424.51 6570.98,3682.96 6570.98,4375.98 v1(6700,4505)
STEP-DOWN1: Q1.2 R15.2 U4.1 U4.7 U4.8 | length 756.2
  Top Layer w40: R15.2 5776.78,4045.22 U4.7
  Top Layer w70: 5735,3805 5735,3756.08 5879.01,3612.07 5879.01,3580.8 Q1.2
  Top Layer w80: 5722.81,3807.19 5722.81,3982.81 5750,4010 5790,4010
SWCLK: R7.2 U2.37 U3.3 | length 440.1
  Top Layer w10: U3.3 3670.63,5459.37 R7.2 3991.25,5459.37 U2.37
SWDIO: R6.2 U2.34 U3.2 | length 525.8
  Top Layer w10: U3.2 3797.75,5560 R6.2 4072.47,5563.64 4122.47,5613.64 4122.47,5617.47 4125,5620 4125,5632.56 U2.34
V-UP: C15.1 C26.1 D3.1 H4.1 H4.2 R15.1 R36.2 U4.6 U18.4 | length 2833.8
  Top Layer w15: U18.4 5798.59,5497.39 5798.59,5262.31 5860,5200.9 v1(5860,5153.61) ; 5870,4485 5870,4755 H4.2
  Top Layer w20: C26.1 5485,4764.99 R36.2
  Top Layer w40: U4.6 5862.74,4159.52 R15.1
  Top Layer w100: D3.1 5333.59,4355.37 ccw(c5333.59,4455.37) 5404.3,4384.66 C26.1 5889.65,4465.35 5905,4450 ; H4.1 H4.2 ; R15.1 5950,4246.78 5950,4449.41 C15.1
  Bottom Layer w15: H4.1 v1@5860,5145
VBAT: U2.1
VCC: C3.2 C4.2 C5.2 C6.2 C7.2 C8.2 C13.2 C21.2 C28.2 H1.1 H1.2 H2.2 LDO1.5 LED1.2 R6.1 R8.2 R14.1 R27.2 R29.1 R31.2 R33.1 R41.1 R42.1 R55.2 R56.1 R57.2 U1.10 U2.9 U2.24 U2.36 U2.48 U3.1 U8.1 U8.5 U12.1 U12.5 U12.7 | length 13020.8
  Top Layer w10: C6.2 4001.88,5700 U2.36 ; U2.48@4233.25,5395.13 4233.25,5396.39 4255.24,5418.39 4255.24,5485.24 4328.49,5558.49 4377.37,5558.49 4403.61,5532.24 4403.61,5525.78 4421.86,5507.52 U2.9@4421.86,5501.48 ; U2.9@4423.52,5501.48 v1(4475,5450) 4482.53,5457.53 4490.05,5457.53 4537.99,5505.48 4537.99,5512.99 4629.37,5604.37 R8.2 4640,5670 4825,5855 5000,5855 5062.23,5792.77 ; U8.1 4995.64,5253.15 4992.01,5249.52 4992.01,5235.41 4969.62,5213.02 ; U8.5 5076.95,5299.9 C21.2 ; v1(5095,5800) 5087.77,5792.77 5062.23,5792.77 ; v1(5185,5840) 5240.63,5784.37 R41.1 ; C28.2 5350.64,5226.27 U12.1 ; U12.7 5409.69,5349.51 5414.2,5345 ; U12.5 5430,5303.1 5430,5329.2 5414.2,5345 ; R14.1@6684.37,4425 6737.48,4478.11 6805,4478.11 ; C13.2 6805,4478.11 ; U1.10 6858.4,4527.07 6819.14,4527.07 6805,4512.93 6805,4478.11 ; 4969.62,5213.02 C21.2 ; 4969.62,5213.02 4941.98,5213.02 4855,5300 4855,5475 4970,5590 5150.63,5590 R42.1 5235.63,5685 5170,5685 5062.23,5792.77 ; C21.2 5165,5301.07 5349.22,5301.07 U12.1 ; U12.1 5350.64,5330.64 5365,5345 5414.2,5345
  Top Layer w15: C4.2@3990.63,5050 3991.39,5050.76 C3.2@3991.39,5127.4 ; U2.24 4354.37,5822.49 C7.2 4390,5915.63 H2.2 ; C28.2 5348.76,5195.61 v1(5450.61,5195.61) ; v1(6535,4375) 6634.37,4375 R14.1@6684.37,4425
  Top Layer w20: LDO1.5 C3.2@3991.39,5127.4 ; C6.2@3999.64,5690.2 3951.81,5642.38 R6.1 3783.76,5660 U3.1 3710,5700 H1.1 H1.2 3825,6085 4330,6085 H2.2 ; R55.2 4035,3692.41 R57.2 3822.11,3975 4115.63,3975 R29.1 ; v1(4180,4135) 4180.63,4134.37 R29.1 ; v1(4210,5200) 4210,5254.37 C5.2 4226.23,5351.86 4226.23,5385.84 U2.48@4229.38,5388.99 ; R56.1 4700,3890.61 ; R31.2 5192.64,4040 5149.54,4083.09 4890.46,4083.09 4847.36,4040 R33.1 4700,3899.37 4700,3890.61 ; R29.1 4240.63,4100 4489.37,4100 R27.2 4698.76,3890.61 4700,3890.61
  Top Layer w30: U3.1 3670,5639.79 3570,5539.79 3570,5380.21 3646.63,5303.58 3884.73,5303.58 LED1.2@3953.31,5235 ; C3.2 3996.39,5191.92 LED1.2@3953.31,5235 ; C5.2 4139.37,5265 4139.37,5259.73 4114.64,5235 LED1.2@3953.31,5235
  Bottom Layer w10: C8.2 4439.37,5485.63 v1(4475,5450) ; v1(5095,5800) 5145,5800 v1(5185,5840)
  Bottom Layer w15: v1(5450.61,5195.61) 6024.39,5195.61 6089.51,5130.49 6089.51,4820.49 v1(6535,4375)
  Bottom Layer w20: v1(4180,4135) 4210,4165 v1(4210,5200)
VOUT: C16.1 H6.1 H6.2 L1.1 L3.1 R18.2 | length 2599.4
  Top Layer w15: v1(6115,4230) 6236.69,4230 L1.1
  Top Layer w20: L3.1@6185.16,4800 6185.16,4955.16 6340,5110 H6.2 H6.1
  Top Layer w100: L3.1 6185.27,4761.62 C16.1 6315,4345.27 L1.1 ; L3.1@6185.16,4800 L3.1@6185.27,4799.89
  Bottom Layer w20: R18.2 5850,3655 6040,3845 6040,4155 v1(6115,4230)
VOUT-FILTER: C34.1 L3.2 U1.1 U1.2 U1.3 | length 574.3
  Top Layer w100: L3.2 6465,4800 ; 6475,4810 6465,4800 ; 6620,4665.95 6536.34,4749.61 ; C34.1 6640,4853.26 6536.34,4749.61 ; 6465,4800 6485.95,4800 6536.34,4749.61
pads on no net: LDO1.4 R18.3 R36.1 U1.13 U8.3 U8.9 U12.3 U12.9 U18.8 U18.9 U18.10 U18.12 U18.13 U18.14

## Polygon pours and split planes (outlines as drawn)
GND on Bottom Layer (solid, remove dead copper, pour order 4): 3000,7085 7645,7085 7645,3015 3000,3015
GND on Top Layer (solid, remove dead copper, pour order 2): 3225,6575 7490,6575 7490,3000 3225,3000
PGND on Top Layer (solid, remove dead copper, pour order 0): 3915,4925 4320,4925 4390,4995 4390,5010 4609.18,5010 4624.64,4994.54 4724.54,4994.54 4830,5100 5105,5100 5110,5105 5295,5105 5315,5125 5380,5125 5405,5150 5560,5150 5605,5105 7283.49,5105 7365,3210 5280,3195 5280,3285 5305,3310 5305,3435 5370,3500 5370,3925 5375,3930 5375,4030 5335,4070 5260,4070 5160,4170 4935,4170 4870,4105 4530,4105 4505,4130 3930,4130 3915,4115 3865,4115 3790,4190 3790,4285.1 3814.19,4309.29 3905,4482.34 3905,4814.61 3915,4824.61

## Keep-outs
Top Layer:
  region: 3810,4405 3885,4405 3885,4393.97 3869.59,4378.56 3860.21,4378.56 3834.01,4352.36 3834.01,4319.47 3836.02,4317.46 3827.37,4308.81 3813.71,4308.81 3813.71,4316.29 3810,4320
Board Outline Layer:
  circle w1: c3550,6130 r43
  region: 3593,6130 cw(c3550,6130) 3507,6130 cw(c3550,6130)
  circle w1: c6950,6125 r43
  region: 6993,6125 cw(c6950,6125) 6907,6125 cw(c6950,6125)
  circle w1: c6950,3330 r43
  region: 6993,3330 cw(c6950,3330) 6907,3330 cw(c6950,3330)
  circle w1: c3550,3330 r43
  region: 3593,3330 cw(c3550,3330) 3507,3330 cw(c3550,3330)
  lines w10: 3450,3330 ccw(c3550,3330) 3550,3230 6950,3230 ccw(c6950,3330) 7050,3330 7050,6130 ccw(c6950,6130) 6950,6230 3550,6230 ccw(c3550,6130) 3450,6130 3450,3330

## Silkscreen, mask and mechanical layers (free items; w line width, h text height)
Top Silkscreen Layer:
  lines w10: 3942.73,5104 4972.73,5104 4972.73,6134 3942.73,6134 3942.73,5104
Bottom Silkscreen Layer:
  text "数控直流电源 / 黄元泽-23211319 / 廖一可-23211326 / 崔以恒-23211288 / 2025/11/23" at 5745,4090 h120
Mechanical Layer:
  circle w1: c3550,6130 r43
  circle w1: c6950,6125 r43
  circle w1: c6950,3330 r43
  circle w1: c3550,3330 r43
